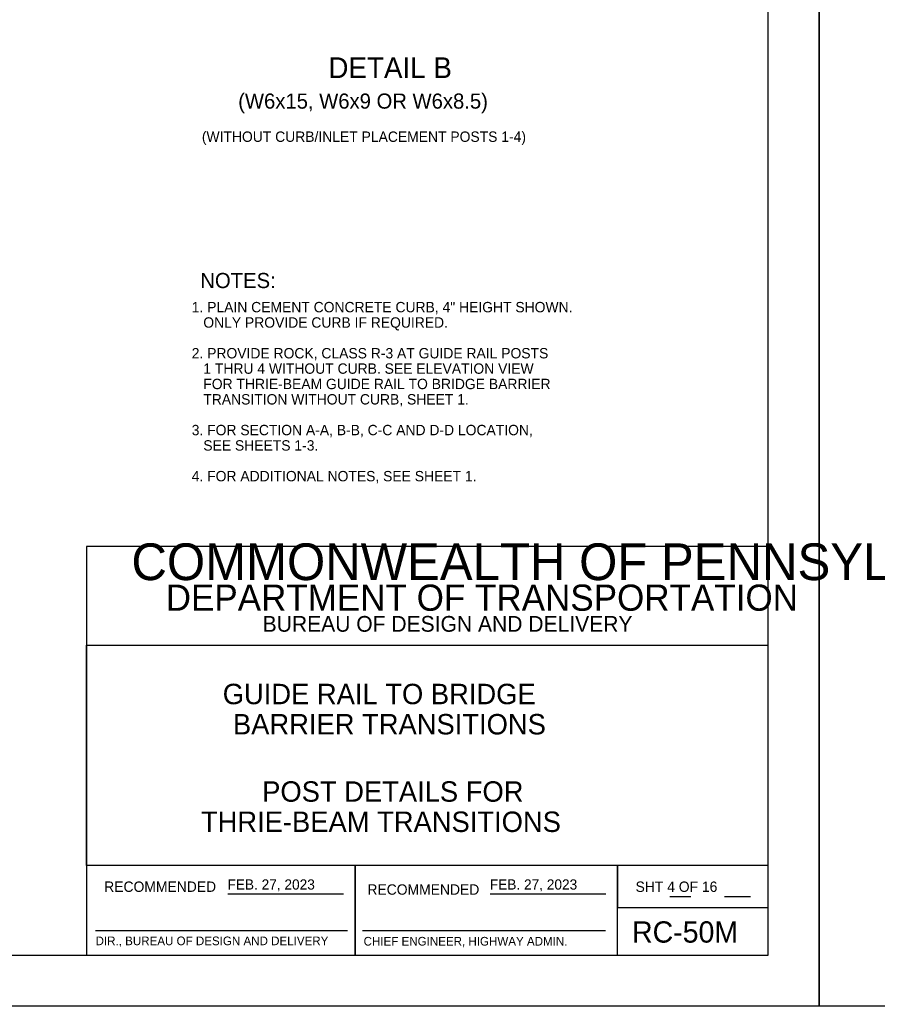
# Model space of a CAD drawing. Extents: x 632007860 to 635435983, y 295418622 to 297794622.
# Drawn here: x 632614236 to 632865880, y 295418622 to 295708328 of the extents above; entities that cross this region are included whole.
import ezdxf

# ---------------------------------------------------------------- set-up
doc = ezdxf.new("R2010")
doc.units = 0
for name, color, linetype in [('1', 7, 'Continuous'), ('2', 7, 'Continuous'), ('PLT-BNDY', 7, 'Continuous'), ('S-DETL-T120', 7, 'Continuous'), ('S-DETL-T175', 7, 'Continuous'), ('S-DETL-T240', 7, 'Continuous')]:
    doc.layers.add(name, color=color, linetype=linetype)

msp = doc.modelspace()

# ---------------------------------------------------------------- linework, layer by layer
at = {"layer": '1'}
for p, q in [((632675325, 295451611), (632709211, 295451611)), ((632752323, 295451611), (632786193, 295451611)), ((632805048, 295450878), (632811190, 295450878)), ((632821049, 295450878), (632828696, 295450878)), ((632636485, 295440918), (632710385, 295440918)), ((632714791, 295440918), (632786131, 295440918))]:
    msp.add_line(p, q, dxfattribs=at)
msp.add_lwpolyline([(632833860, 295433622), (632833860, 295997622), (632047860, 295997622), (632047860, 295433622), (632833860, 295433622), (632833860, 295459981), (632633860, 295459981), (632633860, 295524659), (632833860, 295524659), (632833860, 295553622), (632633860, 295553622), (632633860, 295433622), (632712661, 295433622), (632712661, 295459981), (632712661, 295433622), (632789661, 295433622), (632789661, 295459981), (632789661, 295447665), (632833860, 295447665)], dxfattribs=at)
at = {"layer": 'PLT-BNDY'}
for points in [[(632007860, 296012622), (632848860, 296012622), (632848860, 295418622), (632007860, 295418622)], [(632848860, 296012622), (633689860, 296012622), (633689860, 295418622), (632848860, 295418622)]]:
    msp.add_lwpolyline(points, close=True, dxfattribs=at)

# ---------------------------------------------------------------- texts
at = {"layer": '1'}
for s, height, p in [('COMMONWEALTH OF PENNSYLVANIA', 10783.37, (632647011, 295543766)), ('DEPARTMENT OF TRANSPORTATION', 7684.29, (632657072, 295534771)), ('BUREAU OF DESIGN AND DELIVERY', 4622.09, (632685520, 295528609)), ('RECOMMENDED', 3048, (632639023, 295452216)), ('FEB. 27, 2023', 3000, (632675186, 295452887)), ('RECOMMENDED', 3048, (632716267, 295451379)), ('FEB. 27, 2023', 3000, (632752184, 295452887)), ('SHT 4 OF 16', 3048, (632794952, 295452206)), ('APPROVED', 19.2, (632676883, 295451554)), ('RC-50M', 6250, (632793930, 295437312)), ('DIR., BUREAU OF DESIGN AND DELIVERY', 2540, (632636485, 295436554)), ('CHIEF ENGINEER, HIGHWAY ADMIN.', 2540, (632715144, 295436445))]:
    msp.add_text(s, height=height, dxfattribs=at).set_placement(p)
at = {"layer": '2'}
for s, p in [('GUIDE RAIL TO BRIDGE', (632673804, 295507323)), ('BARRIER TRANSITIONS', (632676804, 295498448)), ('POST DETAILS FOR', (632685376, 295478686)), ('THRIE-BEAM TRANSITIONS', (632667400, 295469804))]:
    msp.add_text(s, height=6000, dxfattribs=at).set_placement(p)
at = {"layer": 'S-DETL-T120'}
msp.add_text('(WITHOUT CURB/INLET PLACEMENT POSTS 1-4)', height=3048.07, dxfattribs=at).set_placement((632667687, 295672461))
for s, p in [(' 1. PLAIN CEMENT CONCRETE CURB, 4" HEIGHT SHOWN. ', (632663574, 295622409)), ('    ONLY PROVIDE CURB IF REQUIRED.', (632663574, 295617896)), (' 2. PROVIDE ROCK, CLASS R-3 AT GUIDE RAIL POSTS', (632663574, 295608872)), ('    1 THRU 4 WITHOUT CURB. SEE ELEVATION VIEW', (632663574, 295604360)), ('    FOR THRIE-BEAM GUIDE RAIL TO BRIDGE BARRIER', (632663574, 295599848)), ('    TRANSITION WITHOUT CURB, SHEET 1.', (632663574, 295595335)), (' 3. FOR SECTION A-A, B-B, C-C AND D-D LOCATION,', (632663574, 295586311)), ('    SEE SHEETS 1-3.', (632663574, 295581799)), (' 4. FOR ADDITIONAL NOTES, SEE SHEET 1.', (632663574, 295572775))]:
    msp.add_text(s, height=3048.06, rotation=360, dxfattribs=at).set_placement(p)
at = {"layer": 'S-DETL-T175'}
msp.add_text('NOTES:', height=4450, dxfattribs=at).set_placement((632667212, 295629520))
at = {"layer": 'S-DETL-T240'}
for s, height, p in [('DETAIL B', 6096, (632704814, 295691196)), ('(W6x15, W6x9 OR W6x8.5)', 4442.45, (632678339, 295682217))]:
    msp.add_text(s, height=height, dxfattribs=at).set_placement(p)

doc.saveas('drawing.dxf')
